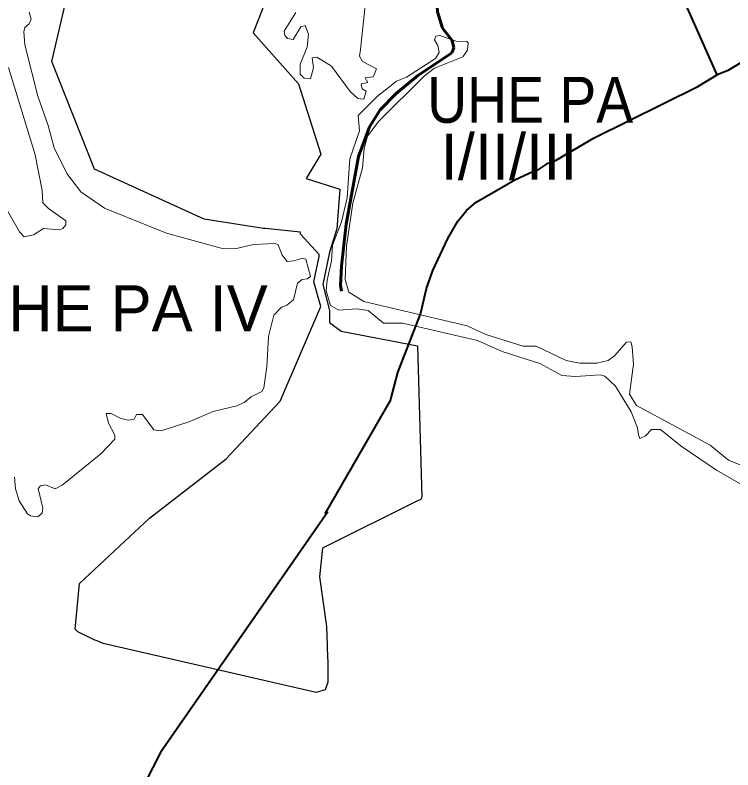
# Model space of a CAD drawing. Extents: x 553962 to 842807, y 8883888 to 9032388.
# Drawn here: x 583762 to 591570, y 8953669 to 8961876 of the extents above; entities that cross this region are included whole.
import ezdxf
from ezdxf.enums import TextEntityAlignment as Align

# ---------------------------------------------------------------- set-up
doc = ezdxf.new("R2010")
doc.units = 0
doc.header["$LTSCALE"] = 200
doc.linetypes.add('LONG_DASH_SHORT_DASH', pattern=[9.9, 6, -1.2, 1.5, -1.2])
for name, color, linetype, lineweight in [('12', 7, 'Continuous', 25), ('21', 7, 'Continuous', 25), ('25', 7, 'Continuous', 13), ('7', 7, 'Continuous', 90)]:
    doc.layers.add(name, color=color, linetype=linetype, lineweight=lineweight)
doc.layers.add('42', color=7, linetype='Continuous')

msp = doc.modelspace()

# ---------------------------------------------------------------- linework, layer by layer
at = {"layer": '12', "lineweight": 40}
for points in [[(588695.4, 8970396.6), (588857.5, 8969895.4), (589190.3, 8968987.7), (589251, 8968710.7), (589674.6, 8967582.3), (589899.5, 8967058.9), (590052.2, 8966645.4), (590154.6, 8966267.7), (590247.4, 8965995.5), (590238.8, 8965878.8), (590381.4, 8965077.2), (590437.7, 8964620.9), (590556.9, 8963909.5), (590712.3, 8962804.7), (590781.8, 8962609.4), (591396.4, 8961227.9)], [(587134, 8956453.8), (587843.6, 8957685.7), (587923.7, 8957988.5), (588169.9, 8958625.1), (588237, 8958904.7), (588304.1, 8959099.5), (588468, 8959448.9), (588578.9, 8959635.8), (588673.7, 8959750.1), (588777.5, 8959843.1), (589203.6, 8960089.7), (589393.4, 8960175.8), (589428.5, 8960178.5), (589560.1, 8960264.6), (589648.9, 8960297.2), (590059.4, 8960543.5), (591188.1, 8961101.4), (591408.7, 8961235.4), (591525.3, 8961280.9), (591868.7, 8961488.1), (592154.1, 8961587.2), (592311.1, 8961655)], [(587162.9, 8956477.1), (585344.2, 8953858.6), (584358.8, 8951929.6)]]:
    msp.add_lwpolyline(points, dxfattribs=at)
at = {"layer": '21'}
for points in [[(586765.6, 8962744.6), (586351.3, 8961682.2), (586846.3, 8961129.9), (587088.5, 8960362.9), (586927, 8960100.5)], [(586058.4, 8957052.4), (586644.6, 8957678.4), (587088.5, 8958707.8), (587013.2, 8958975.6), (587068.3, 8959252.8), (587068.3, 8959273), (586866.5, 8959495), (586866.5, 8959515.2), (586483.1, 8959555.5), (586463, 8959555.5), (585817.3, 8959656.5), (584626.8, 8960201.4), (584162.8, 8961372.1), (584384.7, 8962320.7)], [(586927, 8960100.5), (587293.7, 8959984.2), (587261.8, 8959553.8), (587182.2, 8959298.7), (587110, 8958948.6), (587182.2, 8958662.7), (587182.2, 8958533.5), (587309.6, 8958437.9), (588138.3, 8958278.5)], [(588138.3, 8958278.5), (588184.9, 8956636.2), (588170.1, 8956606.6), (588147.9, 8956599.2), (587104, 8956080.8), (587074.4, 8955769.7), (587148.4, 8955229.1)], [(587148.4, 8955229.1), (587155.8, 8955021.8), (587155.8, 8954992.1), (587163.2, 8954829.2), (587163.2, 8954644.1), (587163.2, 8954621.8), (587133.6, 8954540.4), (587037.4, 8954510.8), (584720.1, 8955044), (584653.5, 8955073.6), (584631.3, 8955081), (584601.7, 8955095.8), (584446.2, 8955169.9), (584416.6, 8955199.5), (584461, 8955695.7), (585223.6, 8956406.6), (586058.4, 8957052.4)]]:
    msp.add_lwpolyline(points, dxfattribs=at)
at = {"layer": '25'}
for points in [[(587781.7, 8962215.1), (587781.7, 8962215.1), (587718.2, 8962140.9), (587735, 8962113.3), (587792.4, 8962083.3), (587794.6, 8962050), (587745.5, 8962032.4), (587597.2, 8962100.2), (587563.1, 8962089.5), (587569.5, 8961975.7), (587540.2, 8961707.3), (587517.7, 8961501.6)], [(587781.7, 8962215.1), (587781.7, 8962215.1), (587718.2, 8962140.9), (587735, 8962113.3), (587792.4, 8962083.3), (587794.6, 8962050), (587745.5, 8962032.4), (587597.2, 8962100.2), (587563.1, 8962089.5), (587569.5, 8961975.7), (587540.2, 8961707.3), (587517.7, 8961501.6)], [(583913.8, 8961907.2), (583936.8, 8961830.6), (583913.5, 8961781.7), (583866.6, 8961740.8), (583856.2, 8961694.6), (583869, 8961554.4), (584009.2, 8960993.4), (584121.2, 8960674.7), (584187.7, 8960432.6), (584325.6, 8960152.6), (584476.5, 8959954.9), (584733.5, 8959776.4), (585408.8, 8959506.7), (586028.5, 8959334.8), (586169.5, 8959338.8), (586356.5, 8959383.4), (586592.2, 8959394), (586621.9, 8959377), (586666.5, 8959264.6), (586719.8, 8959198.7), (586794.3, 8959202.9), (586887.5, 8959234.6), (586924.3, 8959221.3), (586974.5, 8959033.2), (586938.3, 8959007.4), (586883.3, 8959001), (586832.3, 8958962.8), (586791.8, 8958780.2), (586717.8, 8958720.8), (586660.1, 8958701.3), (586577.3, 8958614.2), (586518, 8958381), (586500.9, 8958053.6), (586466.9, 8957824.2), (586445.4, 8957783.8), (586330.8, 8957724.2), (586254.3, 8957662.7), (586173.8, 8957626.7)], [(583913.8, 8961907.2), (583936.8, 8961830.6), (583913.5, 8961781.7), (583866.6, 8961740.8), (583856.2, 8961694.6), (583869, 8961554.4), (584009.2, 8960993.4), (584121.2, 8960674.7), (584187.7, 8960432.6), (584325.6, 8960152.6), (584476.5, 8959954.9), (584733.5, 8959776.4), (585408.8, 8959506.7), (586028.5, 8959334.8), (586169.5, 8959338.8), (586356.5, 8959383.4), (586592.2, 8959394), (586621.9, 8959377), (586666.5, 8959264.6), (586719.8, 8959198.7), (586794.3, 8959202.9), (586887.5, 8959234.6), (586924.3, 8959221.3), (586974.5, 8959033.2), (586938.3, 8959007.4), (586883.3, 8959001), (586832.3, 8958962.8), (586791.8, 8958780.2), (586717.8, 8958720.8), (586660.1, 8958701.3), (586577.3, 8958614.2), (586518, 8958381), (586500.9, 8958053.6), (586466.9, 8957824.2), (586445.4, 8957783.8), (586330.8, 8957724.2), (586254.3, 8957662.7), (586173.8, 8957626.7)], [(587098.4, 8961386.8), (587045, 8961420.4), (586993.8, 8961411.8), (587008.6, 8961303.5), (586976.2, 8961182.7), (586906.7, 8961189.1), (586864.3, 8961233.5), (586864.2, 8961341.7), (586938.6, 8961529.2), (586953.1, 8961669.7), (586916.8, 8961762.6), (586868.3, 8961747.5), (586787.2, 8961611.7), (586725.9, 8961622.5), (586694.3, 8961654.3), (586687.9, 8961700.7), (586815.2, 8961902.8)], [(587098.4, 8961386.8), (587045, 8961420.4), (586993.8, 8961411.8), (587008.6, 8961303.5), (586976.2, 8961182.7), (586906.7, 8961189.1), (586864.3, 8961233.5), (586864.2, 8961341.7), (586938.6, 8961529.2), (586953.1, 8961669.7), (586916.8, 8961762.6), (586868.3, 8961747.5), (586787.2, 8961611.7), (586725.9, 8961622.5), (586694.3, 8961654.3), (586687.9, 8961700.7), (586815.2, 8961902.8)], [(587368.2, 8959365.5), (587437, 8959830.7), (587541.6, 8960215), (587558.8, 8960425), (587596.7, 8960558.6), (587717.4, 8960723.2), (588213.5, 8961217.2), (588323.7, 8961300.9), (588630.6, 8961421.7), (588681.9, 8961493.8), (588689.2, 8961575.7), (588675.2, 8961590.7), (588561, 8961592.8), (588381.1, 8961656.2), (588338.6, 8961648.6), (588325.4, 8961606.6), (588359, 8961544.8), (588373.9, 8961471.3), (588335.7, 8961403.9), (588018, 8961201.6), (587911.6, 8961156.7), (587701, 8960992.4), (587493.3, 8960783.2), (587506.9, 8960616.2), (587403.7, 8960314.5), (587373.8, 8959887.7), (587311.1, 8959628.3), (587213.9, 8959375.4), (587204.9, 8959204), (587155.6, 8958993.5), (587145.5, 8958878.4), (587193.6, 8958719.2), (587281.8, 8958666.6), (587474.7, 8958681.2), (587603.9, 8958663), (587767.8, 8958525.1), (587976.7, 8958527.1), (588793.4, 8958337.9), (589059.2, 8958220.1), (589471.1, 8958087), (589708, 8957957.9), (589856.5, 8957947.6), (590127.1, 8957964.8), (590176.9, 8957951.8), (590291.3, 8957841.5), (590464.7, 8957564.3), (590533, 8957388.3), (590544.4, 8957313.3), (590557.7, 8957273.4), (590617.6, 8957300), (590684.2, 8957372.3), (590781.5, 8957369.6), (591005.6, 8957189.1), (591390.8, 8956926.9), (591724.8, 8956737.2)], [(587517.7, 8961501.6), (587510, 8961431.2), (587539.9, 8961371.6), (587692.7, 8961292.6), (587670.8, 8961239.2)], [(587517.7, 8961501.6), (587510, 8961431.2), (587539.9, 8961371.6), (587692.7, 8961292.6), (587670.8, 8961239.2)], [(587670.8, 8961239.2), (587656.4, 8961204.1), (587570.6, 8961194.6), (587599.2, 8961141.8), (587527.1, 8961129.4), (587535.4, 8961074.6), (587582.5, 8961050.1), (587556.1, 8960961.2), (587491.1, 8960968.1), (587408.1, 8961044.4), (587205.3, 8961319.5), (587098.4, 8961386.8)], [(587670.8, 8961239.2), (587656.4, 8961204.1), (587570.6, 8961194.6), (587599.2, 8961141.8), (587527.1, 8961129.4), (587535.4, 8961074.6), (587582.5, 8961050.1), (587556.1, 8960961.2), (587491.1, 8960968.1), (587408.1, 8961044.4), (587205.3, 8961319.5), (587098.4, 8961386.8)], [(583684, 8959740.2), (583809.5, 8959521.5), (583862.6, 8959466.3), (583962.4, 8959487.6), (584070.6, 8959557.6), (584244.7, 8959542.8), (584281, 8959557.7), (584312.8, 8959595.8), (584315, 8959638.2), (584126, 8959774.3), (584064.3, 8959836.4), (584055.9, 8959969.5), (583979.3, 8960356.6), (583690.5, 8961308.2)], [(583684, 8959740.2), (583809.5, 8959521.5), (583862.6, 8959466.3), (583962.4, 8959487.6), (584070.6, 8959557.6), (584244.7, 8959542.8), (584281, 8959557.7), (584312.8, 8959595.8), (584315, 8959638.2), (584126, 8959774.3), (584064.3, 8959836.4), (584055.9, 8959969.5), (583979.3, 8960356.6), (583690.5, 8961308.2)], [(591853.4, 8956904.4), (591520.9, 8957037.4), (591321.1, 8957200.7), (590522.6, 8957630), (590445.4, 8957756.5), (590486.6, 8958082.5), (590475.5, 8958269.4), (590460, 8958322.7), (590411.3, 8958320.8), (590281.4, 8958169.9), (590213.4, 8958120.7), (590089.5, 8958093.2), (589901.7, 8958091.4), (589756.1, 8958120.1), (589428.5, 8958275.3), (589288.6, 8958277.6), (588883.2, 8958402.7), (588677.6, 8958496.7), (587555.9, 8958762.2), (587392.7, 8958862), (587351, 8959003.1), (587368.2, 8959365.5)], [(586173.8, 8957626.7), (585918.1, 8957564.8), (585664, 8957458.9), (585351.4, 8957354.8), (585272.9, 8957365.6), (585149.7, 8957533.1), (585084, 8957533), (585058.5, 8957484.5), (584997.2, 8957473.7), (584911.7, 8957490.8), (584806, 8957543.7), (584753, 8957543.8), (584778.1, 8957437.9), (584848.5, 8957309.3), (584847.7, 8957267), (584696, 8957104.7), (584274.9, 8956764.4), (584197.5, 8956726), (584094.1, 8956768.4), (584038.7, 8956757.6), (584011.4, 8956727.3), (584062.2, 8956515.4), (584055.8, 8956462.4), (584011.2, 8956420.2), (583928.7, 8956432.8), (583896.6, 8956454.1), (583805.3, 8956596.4), (583767, 8956723.9), (583756.3, 8956851.3)], [(586173.8, 8957626.7), (585918.1, 8957564.8), (585664, 8957458.9), (585351.4, 8957354.8), (585272.9, 8957365.6), (585149.7, 8957533.1), (585084, 8957533), (585058.5, 8957484.5), (584997.2, 8957473.7), (584911.7, 8957490.8), (584806, 8957543.7), (584753, 8957543.8), (584778.1, 8957437.9), (584848.5, 8957309.3), (584847.7, 8957267), (584696, 8957104.7), (584274.9, 8956764.4), (584197.5, 8956726), (584094.1, 8956768.4), (584038.7, 8956757.6), (584011.4, 8956727.3), (584062.2, 8956515.4), (584055.8, 8956462.4), (584011.2, 8956420.2), (583928.7, 8956432.8), (583896.6, 8956454.1), (583805.3, 8956596.4), (583767, 8956723.9), (583756.3, 8956851.3)]]:
    msp.add_lwpolyline(points, dxfattribs=at)
at = {"layer": '7', "linetype": 'LONG_DASH_SHORT_DASH', "lineweight": 60}
msp.add_lwpolyline([(587540.9, 8964040.5), (587545.5, 8964019), (587739.9, 8963466), (587828.5, 8963155), (587886.8, 8963016.8), (588023, 8962809.1), (588321.3, 8962515.1), (588353.7, 8962454.8), (588379.7, 8962350), (588349.5, 8962039.7), (588356.1, 8961913.4), (588409.9, 8961732.7), (588515.9, 8961598.5), (588533, 8961520.2), (588511.4, 8961464.3), (588140, 8961216), (587908.2, 8961023.1), (587733.4, 8960846.2), (587616.5, 8960660), (587498.3, 8960337.4), (587362.2, 8959603), (587314, 8959147.2), (587303.2, 8958935.8), (587310.7, 8958873)], dxfattribs=at)

# ---------------------------------------------------------------- texts
at = {"layer": '42', "width": 0.9}
msp.add_text('UHE PA', height=500, dxfattribs=at).set_placement((589364.5, 8960705), align=Align.CENTER)
at = {"layer": '42'}
for s, p in [('I/II/III', (589134.4, 8960086.2)), ('UHE PA IV', (584857.3, 8958438.7))]:
    msp.add_text(s, height=500, dxfattribs=at).set_placement(p, align=Align.CENTER)

doc.saveas('drawing.dxf')
